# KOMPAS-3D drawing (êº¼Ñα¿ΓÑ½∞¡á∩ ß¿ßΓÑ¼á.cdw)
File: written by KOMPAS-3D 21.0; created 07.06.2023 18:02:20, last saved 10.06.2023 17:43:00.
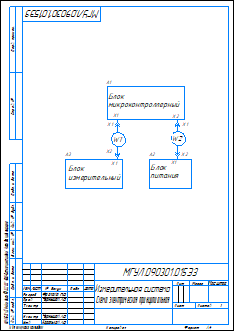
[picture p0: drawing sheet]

Sheet 1: A4, portrait

Document properties: Полное имя файла: C:\Artanis\Учеба\Чертежи\Измерительная система.cdw

Title block, sheet 1: Наименование: Измерительная система / Схема электрическая принципиальная; designation: МГУЛ.090301.015ЭЗ; Количество листов документа: 1; Форматы листов документа: A4; stored path: C:\Artanis\Учеба\Чертежи\общий.cdw; Разработал: Фролова П.В.; Проверил: Чернышов А.В.; Н. контр.: Чернышов А.В.; Утвердил: Корольков А.В,

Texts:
  Блок
  микроконтроллерный
  питания
  измерительный
Dimensions and other numbers on the sheet: 1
